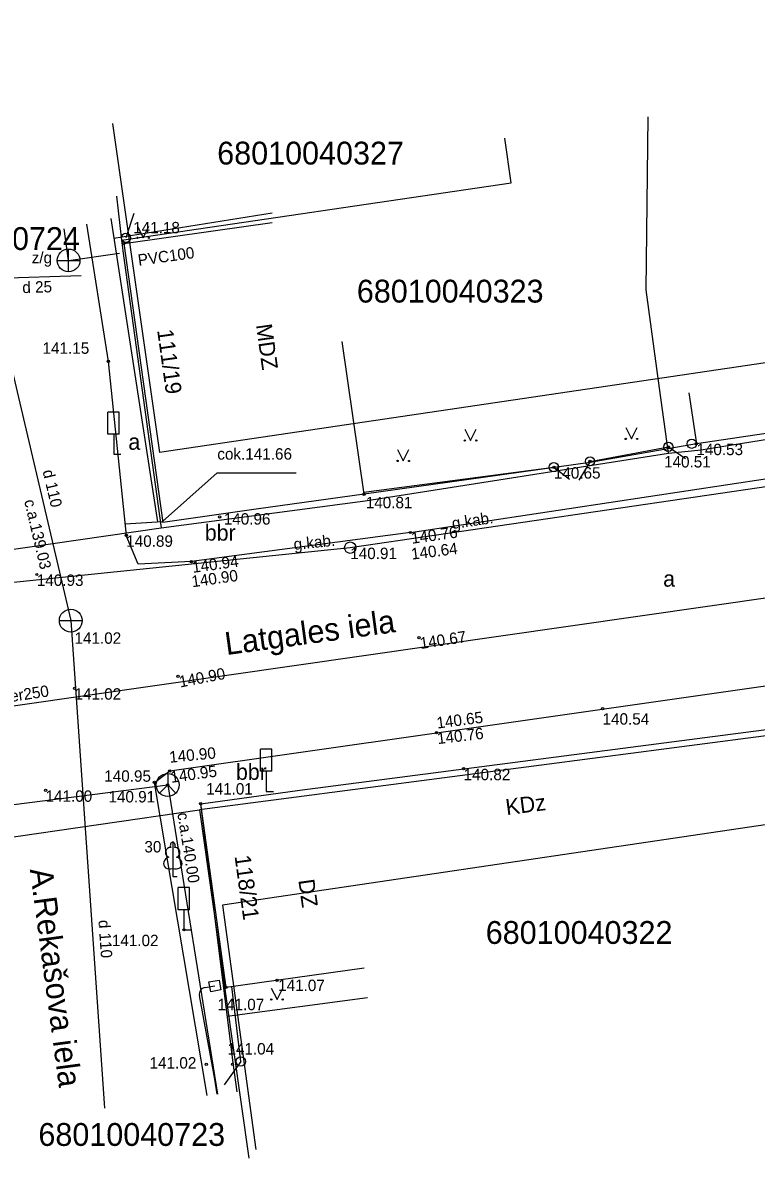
# Model space of a CAD drawing. Extents: x 728785 to 728985, y 273137 to 273208.
# Drawn here: x 728810.66 to 728842.8, y 273138.43 to 273188.14 of the extents above; entities that cross this region are included whole.
import ezdxf

# ---------------------------------------------------------------- set-up
doc = ezdxf.new("R2010")
doc.units = 0
for name, color, linetype in [('APGR_SARK_####_####_#', 7, 'Continuous'), ('BUVE_BDET_####_####_#', 7, 'Continuous'), ('BUVE_BDET_####_TKST_#', 7, 'Continuous'), ('BUVE_EKAS_####_####_#', 7, 'Continuous'), ('BUVE_EKAS_ADRS_TKST_#', 7, 'Continuous'), ('BUVE_EKAS_RAKS_TKST_#', 7, 'Continuous'), ('CELI_CAPM_####_####_#', 7, 'Continuous'), ('CELI_CMAL_####_####_#', 7, 'Continuous'), ('CELI_CSEG_####_TKST_#', 7, 'Continuous'), ('CELI_ELEM_####_####_#', 7, 'Continuous'), ('CELI_IELA_####_TKST_#', 7, 'Continuous'), ('ELEK_ACRL_####_####_#', 7, 'Continuous'), ('ELEK_ELEM_####_####_#', 7, 'Continuous'), ('ELEK_VADP_ZSPR_####_I', 7, 'Continuous'), ('ELEK_VADV_ZSPR_####_#', 7, 'Continuous'), ('ELEK_VADV_ZSPR_TKST_#', 7, 'Continuous'), ('NORB_ELEM_####_####_#', 7, 'Continuous'), ('NORB_ZOGS_KOKA_####_#', 7, 'Continuous'), ('RELJ_AATZ_####_TKST_#', 7, 'Continuous'), ('RELJ_ELEM_####_####_#', 7, 'Continuous'), ('ROBZ_KADS_####_TKST_#', 7, 'Continuous'), ('ROBZ_UZMR_####_####_#', 7, 'Continuous'), ('SAKK_ELEM_####_####_#', 7, 'Continuous'), ('SAKK_ELEM_####_TKST_#', 7, 'Continuous'), ('SAKK_KKAN_####_####_#', 7, 'Continuous'), ('SAKK_KKAN_####_TKST_#', 7, 'Continuous'), ('SKAN_ELEM_####_####_#', 7, 'Continuous'), ('SKAN_VADP_PAST_####_#', 7, 'Continuous'), ('SKAN_VADP_PAST_TKST_#', 7, 'Continuous'), ('TERT_DIAM_####_TKST_#', 7, 'Continuous'), ('TERT_ELEM_####_####_#', 7, 'Continuous'), ('UDTK_ELEM_####_####_#', 7, 'Continuous'), ('UDTK_ELEM_####_TKST_#', 7, 'Continuous'), ('UDTK_VADP_UDEN_####_#', 7, 'Continuous'), ('UDTK_VADP_UDEN_TKST_#', 7, 'Continuous')]:
    doc.layers.add(name, color=color, linetype=linetype)

msp = doc.modelspace()

# ---------------------------------------------------------------- linework, layer by layer
at = {"layer": 'APGR_SARK_####_####_#'}
for points in [[(728955.084, 273187.77), (728943.86, 273188.14), (728816.642, 273169.324)], [(728814.594, 273183.733), (728816.642, 273169.324)], [(728957.827, 273167.668), (728945.002, 273168.092), (728819.408, 273149.515)], [(728819.408, 273149.515), (728820.876, 273138.81)]]:
    msp.add_lwpolyline(points, dxfattribs=at)
at = {"layer": 'BUVE_BDET_####_####_#'}
for points in [[(728816.787, 273166.308), (728819.17, 273168.442), (728820.642, 273168.442)], [(728820.642, 273168.442), (728822.637, 273168.442)]]:
    msp.add_lwpolyline(points, dxfattribs=at)
at = {"layer": 'BUVE_EKAS_####_####_#'}
for p, q in [((728819.004, 273179.025), (728821.592, 273179.387)), ((728815.084, 273178.476), (728819.004, 273179.025)), ((728815.084, 273178.476), (728816.793, 273166.265)), ((728825.614, 273167.499), (728824.647, 273174.186)), ((728839.843, 273171.934), (728840.171, 273169.71)), ((728850.675, 273171.26), (728840.171, 273169.71)), ((728825.614, 273167.499), (728820.89, 273166.838)), ((728820.89, 273166.838), (728816.793, 273166.265)), ((728822.792, 273154.55), (728843.456, 273157.227)), ((728818.457, 273153.951), (728822.792, 273154.55)), ((728819.568, 273145.912), (728818.457, 273153.951)), ((728825.616, 273146.748), (728819.568, 273145.912))]:
    msp.add_line(p, q, dxfattribs=at)
at = {"layer": 'CELI_CAPM_####_####_#'}
for p, q in [((728828.784, 273157.056), (728855.438, 273160.854)), ((728817.1, 273155.387), (728828.784, 273157.056))]:
    msp.add_line(p, q, dxfattribs=at)
for points in [[(728827.643, 273165.823), (728857.186, 273170.288)], [(728827.643, 273165.823), (728818.046, 273164.552), (728815.721, 273164.442)]]:
    msp.add_lwpolyline(points, dxfattribs=at)
at = {"layer": 'CELI_CMAL_####_####_#'}
for p, q in [((728814.523, 273179.564), (728816.564, 273166.293)), ((728815.14, 273166.2), (728816.787, 273166.308)), ((728815.721, 273164.442), (728815.192, 273165.697)), ((728816.423, 273154.886), (728817.1, 273155.387)), ((728818.738, 273141.18), (728816.423, 273154.886)), ((728819.87, 273142.614), (728818.457, 273153.951)), ((728819.616, 273144.651), (728825.761, 273145.463)), ((728820.045, 273141.342), (728819.87, 273142.614))]:
    msp.add_line(p, q, dxfattribs=at)
for points in [[(728814.655, 273178.703), (728821.579, 273179.812)], [(728813.444, 273179.327), (728814.407, 273173.315), (728815.192, 273165.697)], [(728840.171, 273169.71), (728835.511, 273168.888), (728825.614, 273167.499)]]:
    msp.add_lwpolyline(points, dxfattribs=at)
at = {"layer": 'CELI_ELEM_####_####_#'}
for p, q in [((728814.889, 273171.098), (728814.389, 273171.098)), ((728814.389, 273170.129), (728814.389, 273171.098)), ((728814.889, 273170.129), (728814.889, 273171.098)), ((728814.889, 273170.129), (728814.389, 273170.129)), ((728814.643, 273170.129), (728814.643, 273169.251)), ((728814.643, 273169.251), (728814.958, 273169.251)), ((728821.572, 273156.338), (728821.072, 273156.338)), ((728821.072, 273155.369), (728821.072, 273156.338)), ((728821.572, 273155.369), (728821.572, 273156.338)), ((728821.572, 273155.369), (728821.072, 273155.369)), ((728821.326, 273155.369), (728821.326, 273154.491)), ((728821.326, 273154.491), (728821.641, 273154.491)), ((728817.965, 273150.276), (728817.465, 273150.276)), ((728817.465, 273149.307), (728817.465, 273150.276)), ((728817.965, 273149.307), (728817.965, 273150.276)), ((728817.965, 273149.307), (728817.465, 273149.307)), ((728817.719, 273149.307), (728817.719, 273148.429)), ((728817.719, 273148.429), (728818.034, 273148.429))]:
    msp.add_line(p, q, dxfattribs=at)
at = {"layer": 'ELEK_ACRL_####_####_#'}
msp.add_lwpolyline([(728818.916, 273142.762), (728819.077, 273141.897), (728819.172, 273141.234)], dxfattribs=at)
at = {"layer": 'ELEK_ELEM_####_####_#'}
msp.add_lwpolyline([(728819.334, 273145.797), (728818.894, 273145.717), (728818.816, 273146.149), (728819.256, 273146.229)], close=True, dxfattribs=at)
msp.add_circle((728825.007, 273165.16), 0.25, dxfattribs=at)
at = {"layer": 'ELEK_VADP_ZSPR_####_I'}
for points in [[(728819.172, 273141.234), (728819.077, 273141.897), (728818.397, 273145.555)], [(728818.646, 273145.906), (728819.075, 273145.973)]]:
    msp.add_lwpolyline(points, dxfattribs=at)
msp.add_arc((728818.692, 273145.609), 0.3, 98.9045, 190.5262, dxfattribs=at)
at = {"layer": 'ELEK_VADV_ZSPR_####_#'}
for p, q in [((728825.007, 273165.16), (728864.528, 273170.982)), ((728807.375, 273163.351), (728825.007, 273165.16))]:
    msp.add_line(p, q, dxfattribs=at)
at = {"layer": 'NORB_ELEM_####_####_#'}
for p, q in [((728815.519, 273179.782), (728815.179, 273178.724)), ((728838.945, 273169.572), (728839.692, 273169.059)), ((728835.511, 273168.938), (728835.025, 273168.119)), ((728833.927, 273168.682), (728834.612, 273168.157)), ((728820.21, 273142.669), (728819.481, 273141.65))]:
    msp.add_line(p, q, dxfattribs=at)
for centre in [(728815.179, 273178.724), (728839.969, 273169.709), (728838.945, 273169.572), (728833.927, 273168.682), (728835.511, 273168.938), (728820.21, 273142.669)]:
    msp.add_circle(centre, 0.202, dxfattribs=at)
at = {"layer": 'NORB_ZOGS_KOKA_####_#'}
for points in [[(728835.511, 273168.938), (728838.945, 273169.572)], [(728825.602, 273167.583), (728833.927, 273168.682)], [(728820.21, 273142.669), (728819.812, 273145.946)]]:
    msp.add_lwpolyline(points, dxfattribs=at)
at = {"layer": 'RELJ_ELEM_####_####_#'}
for centre in [(728815.084, 273178.476), (728814.407, 273173.315), (728838.945, 273169.572), (728840.171, 273169.71), (728835.511, 273168.938), (728833.927, 273168.682), (728825.614, 273167.499), (728819.279, 273166.508), (728827.643, 273165.823), (728815.192, 273165.697), (728818.046, 273164.552), (728811.275, 273163.985), (728828.019, 273161.216), (728817.463, 273159.527), (728812.926, 273159.005), (728836.061, 273158.117), (728828.784, 273157.056), (728817.1, 273155.387), (728829.974, 273155.48), (728816.423, 273154.886), (728811.656, 273154.535), (728817.008, 273154.772), (728818.457, 273153.951), (728817.719, 273148.429), (728821.801, 273146.221), (728819.568, 273145.912), (728818.698, 273142.537), (728819.847, 273142.537)]:
    msp.add_circle(centre, 0.05, dxfattribs=at)
at = {"layer": 'ROBZ_UZMR_####_####_#'}
for p, q in [((728837.969, 273176.45), (728838.058, 273184.022)), ((728832.052, 273181.133), (728831.782, 273183.086)), ((728814.987, 273178.617), (728832.052, 273181.133)), ((728814.77, 273180.55), (728814.987, 273178.617)), ((728814.987, 273178.617), (728815.04, 273178.148)), ((728815.04, 273178.148), (728816.724, 273166.025)), ((728838.56, 273172.135), (728837.969, 273176.45)), ((728838.948, 273169.303), (728838.56, 273172.135)), ((728840.383, 273169.447), (728850.622, 273171.096)), ((728838.948, 273169.303), (728840.383, 273169.447)), ((728825.66, 273167.215), (728838.948, 273169.303)), ((728816.724, 273166.025), (728825.66, 273167.215)), ((728804.732, 273164.296), (728816.724, 273166.025)), ((728843.441, 273156.952), (728818.395, 273153.682)), ((728806.506, 273151.952), (728818.395, 273153.682)), ((728818.395, 273153.682), (728819.556, 273145.531)), ((728819.556, 273145.531), (728820.561, 273138.429))]:
    msp.add_line(p, q, dxfattribs=at)
at = {"layer": 'SAKK_ELEM_####_####_#'}
msp.add_line((728817.008, 273154.772), (728817.362, 273154.418), dxfattribs=at)
msp.add_lwpolyline([(728817.008, 273155.272), (728817.008, 273154.772), (728816.654, 273154.418)], dxfattribs=at)
msp.add_circle((728817.008, 273154.772), 0.5, dxfattribs=at)
at = {"layer": 'SAKK_KKAN_####_####_#'}
msp.add_lwpolyline([(728790.691, 273151.419), (728817.008, 273154.772), (728819.184, 273141.235)], dxfattribs=at)
at = {"layer": 'SKAN_ELEM_####_####_#'}
for p, q in [((728812.664, 273177.233), (728812.664, 273178.233)), ((728812.164, 273177.733), (728813.164, 273177.733))]:
    msp.add_line(p, q, dxfattribs=at)
msp.add_circle((728812.664, 273177.733), 0.5, dxfattribs=at)
at = {"layer": 'SKAN_VADP_PAST_####_#'}
for points in [[(728812.664, 273177.733), (728812.471, 273179.114)], [(728812.664, 273177.733), (728814.892, 273178.045)], [(728790.054, 273155.22), (728804.423, 273157.397), (728858.768, 273165.198)]]:
    msp.add_lwpolyline(points, dxfattribs=at)
at = {"layer": 'TERT_ELEM_####_####_#'}
for p, q in [((728815.686, 273179.227), (728815.936, 273178.727)), ((728815.936, 273178.727), (728816.186, 273179.227)), ((728830.027, 273170.349), (728830.277, 273169.849)), ((728830.277, 273169.849), (728830.527, 273170.349)), ((728837.075, 273170.419), (728837.325, 273169.919)), ((728837.325, 273169.919), (728837.575, 273170.419)), ((728827.08, 273169.456), (728827.33, 273168.956)), ((728827.33, 273168.956), (728827.58, 273169.456)), ((728817.229, 273151.113), (728817.229, 273150.766)), ((728817.229, 273150.766), (728817.429, 273150.766)), ((728821.548, 273145.879), (728821.798, 273145.379)), ((728821.798, 273145.379), (728822.048, 273145.879))]:
    msp.add_line(p, q, dxfattribs=at)
for points in [[(728817.229, 273152.266), (728817.229, 273151.113)], [(728817.319, 273152.034), (728817.318, 273152.035)]]:
    msp.add_lwpolyline(points, dxfattribs=at)
for centre, radius in [((728815.685, 273178.727), 0.028), ((728816.185, 273178.727), 0.0263), ((728830.027, 273169.848), 0.028), ((728830.527, 273169.848), 0.0263), ((728837.075, 273169.919), 0.028), ((728837.575, 273169.919), 0.0263), ((728827.08, 273168.956), 0.028), ((728827.58, 273168.956), 0.0263), ((728821.548, 273145.378), 0.028), ((728822.048, 273145.378), 0.0263)]:
    msp.add_circle(centre, radius, dxfattribs=at)
for centre, major_axis, ratio, start_param, end_param in [((728817.101, 273151.821), (-0.039, -0.212), 0.861323, 3.141593, 6.283185), ((728817.229, 273152.116), (0, -0.15), 0.707107, 3.14537, 5.287485), ((728817.229, 273152.116), (0, -0.15), 0.707107, 0.995701, 3.137816), ((728817.357, 273151.821), (0.039, -0.212), 0.861323, 0, 3.141593), ((728817.139, 273151.359), (0.307, 0.095), 0.814445, 1.570796, 4.752015), ((728817.319, 273151.359), (-0.307, 0.095), 0.814445, 1.531171, 4.712389)]:
    msp.add_ellipse(centre, major_axis=major_axis, ratio=ratio, start_param=start_param, end_param=end_param, dxfattribs=at)
at = {"layer": 'UDTK_ELEM_####_####_#'}
msp.add_line((728812.262, 273161.966), (728813.262, 273161.966), dxfattribs=at)
msp.add_circle((728812.762, 273161.966), 0.5, dxfattribs=at)
at = {"layer": 'UDTK_VADP_UDEN_####_#'}
msp.add_line((728809.225, 273176.951), (728813.21, 273177.07), dxfattribs=at)
for points in [[(728809.225, 273176.951), (728812.761, 273161.966)], [(728812.761, 273161.966), (728814.241, 273140.623)]]:
    msp.add_lwpolyline(points, dxfattribs=at)

# ---------------------------------------------------------------- texts
at = {"layer": 'BUVE_BDET_####_TKST_#'}
msp.add_text('cok.141.66', height=0.5, dxfattribs=at).set_placement((728819.183, 273169.013))
at = {"layer": 'BUVE_EKAS_ADRS_TKST_#'}
for s, rotation, p in [('111/19', 277.967, (728816.544, 273174.677)), ('118/21', 277.866, (728819.936, 273151.657))]:
    msp.add_text(s, height=0.7, rotation=rotation, dxfattribs=at).set_placement(p)
at = {"layer": 'BUVE_EKAS_RAKS_TKST_#'}
for s, rotation, p in [('MDZ', 277.967, (728820.872, 273174.911)), ('KDz', 7.3818, (728831.858, 273153.449)), ('DZ', 277.866, (728822.73, 273150.604))]:
    msp.add_text(s, height=0.7, rotation=rotation, dxfattribs=at).set_placement(p)
at = {"layer": 'CELI_CSEG_####_TKST_#'}
for s, p in [('a', (728815.284, 273169.444)), ('bbr', (728818.634, 273165.467)), ('a', (728838.716, 273163.451)), ('bbr', (728819.999, 273154.996))]:
    msp.add_text(s, height=0.7, dxfattribs=at).set_placement(p)
at = {"layer": 'CELI_IELA_####_TKST_#'}
for s, rotation, p in [('Latgales iela', 7.723, (728819.581, 273160.456)), ('A.Rekašova iela', 277.641, (728810.965, 273151.073))]:
    msp.add_text(s, height=1, rotation=rotation, dxfattribs=at).set_placement(p)
at = {"layer": 'ELEK_VADV_ZSPR_TKST_#'}
for rotation, p in [(8.3802, (728829.497, 273165.973)), (5.8579, (728822.551, 273165.059))]:
    msp.add_text('g.kab.', height=0.5, rotation=rotation, dxfattribs=at).set_placement(p)
at = {"layer": 'RELJ_AATZ_####_TKST_#'}
for s, p in [(' 141.18', (728815.311, 273178.919)), (' 141.15', (728811.342, 273173.647)), ('140.53', (728840.171, 273169.21)), ('140.51', (728838.755, 273168.669)), ('140.65', (728833.927, 273168.182)), ('140.81', (728825.686, 273166.884)), (' 140.96', (728819.279, 273166.169)), ('140.89', (728815.192, 273165.197)), ('140.91', (728825.007, 273164.66)), ('140.93', (728811.275, 273163.485)), ('141.02', (728812.926, 273158.505)), ('140.54', (728836.061, 273157.412)), ('140.82', (728829.974, 273154.98)), ('141.00', (728811.656, 273154.035)), ('140.91', (728814.413, 273154.007)), (' 141.01', (728818.506, 273154.352)), (' 141.02', (728814.376, 273147.715)), (' 141.07', (728821.661, 273145.749)), (' 141.07', (728819.006, 273144.912)), (' 141.04', (728819.44, 273142.972)), (' 141.02', (728816.031, 273142.357))]:
    msp.add_text(s, height=0.5, dxfattribs=at).set_placement(p)
for s, rotation, p in [('140.76', 7.7223, (728827.71, 273165.328)), ('140.64', 7.1714, (728827.705, 273164.633)), ('140.94', 7.6588, (728818.113, 273164.056)), ('140.90', 7.9333, (728818.087, 273163.425)), ('140.67', 8.6114, (728828.094, 273160.722)), ('140.90', 10.7982, (728817.557, 273159.036)), ('140.65', 7.2808, (728828.82, 273157.238)), ('140.76', 6.5645, (728828.841, 273156.559)), ('140.90', 5.4447, (728817.101, 273155.742)), ('140.95', 7.8353, (728817.166, 273154.864))]:
    msp.add_text(s, height=0.5, rotation=rotation, dxfattribs=at).set_placement(p)
at = {"layer": 'ROBZ_KADS_####_TKST_#'}
for s, p in [('68010040327', (728819.177, 273181.932)), ('68010040724', (728804.981, 273178.19)), ('68010040323', (728825.295, 273175.889)), ('68010040322', (728830.942, 273147.814)), ('68010040723', (728811.343, 273138.971))]:
    msp.add_text(s, height=1, dxfattribs=at).set_placement(p)
at = {"layer": 'SAKK_ELEM_####_TKST_#'}
msp.add_text(' 140.95', height=0.5, dxfattribs=at).set_placement((728814.044, 273154.913))
at = {"layer": 'SAKK_KKAN_####_TKST_#'}
msp.add_text('c.a.140.00', height=0.5, rotation=279.1332, dxfattribs=at).set_placement((728817.428, 273153.529))
at = {"layer": 'SKAN_VADP_PAST_TKST_#'}
for s, rotation, p in [('PVC100', 7.967, (728815.738, 273177.496)), ('ker250', 8.258, (728809.808, 273158.357))]:
    msp.add_text(s, height=0.5, rotation=rotation, dxfattribs=at).set_placement(p)
msp.add_text('z/g', height=0.5, dxfattribs=at).set_placement((728811.05, 273177.609))
at = {"layer": 'TERT_DIAM_####_TKST_#'}
msp.add_text('30', height=0.5, dxfattribs=at).set_placement((728815.988, 273151.817))
at = {"layer": 'UDTK_ELEM_####_TKST_#'}
msp.add_text('141.02', height=0.5, dxfattribs=at).set_placement((728812.926, 273160.952))
at = {"layer": 'UDTK_VADP_UDEN_TKST_#'}
for s, rotation, p in [('d 25', 1.7105, (728810.647, 273176.302)), ('d 110', 283.2772, (728811.524, 273168.512)), ('c.a.139.03', 283.2772, (728810.715, 273167.21)), ('d 110', 273.967, (728813.971, 273148.847))]:
    msp.add_text(s, height=0.5, rotation=rotation, dxfattribs=at).set_placement(p)

doc.saveas('drawing.dxf')
